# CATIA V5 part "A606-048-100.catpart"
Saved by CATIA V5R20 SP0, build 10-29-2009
Part number: A606-048-100
Source: Unknown
Property "ARTICLENO": "A606-048-100"
Property "BOMINFO": "A606-048-100"
Property "CODE": "A606-048-100"
Property "HOLES": "2"
Property "L": "100.000"
Property "L1": "25.000"
Property "L2": "50.000"
Property "LINA": "A606-048-100"
Property "NB": "A606-048-100"
Property "NBSYN": "$CODE."
Property "NN": "A606"
Property "NT": "Wear Plates, self-lubricating"
Property "SCREW": "2xM6"
Property "SUPPLIER": "CF"
Property "W": "48.000"
Bounding box of the stored display mesh (mm): x -24 to 24, y -5 to 5, z -50 to 50
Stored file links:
  C:\Users\Utente\Desktop\3D files A606\A606-048-100.catpart
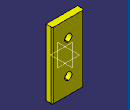
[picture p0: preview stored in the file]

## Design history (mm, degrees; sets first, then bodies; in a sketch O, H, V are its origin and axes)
Body1 "Geometry.1" (main body)
  Solid1 "A606-048-100.catpart": solid without history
